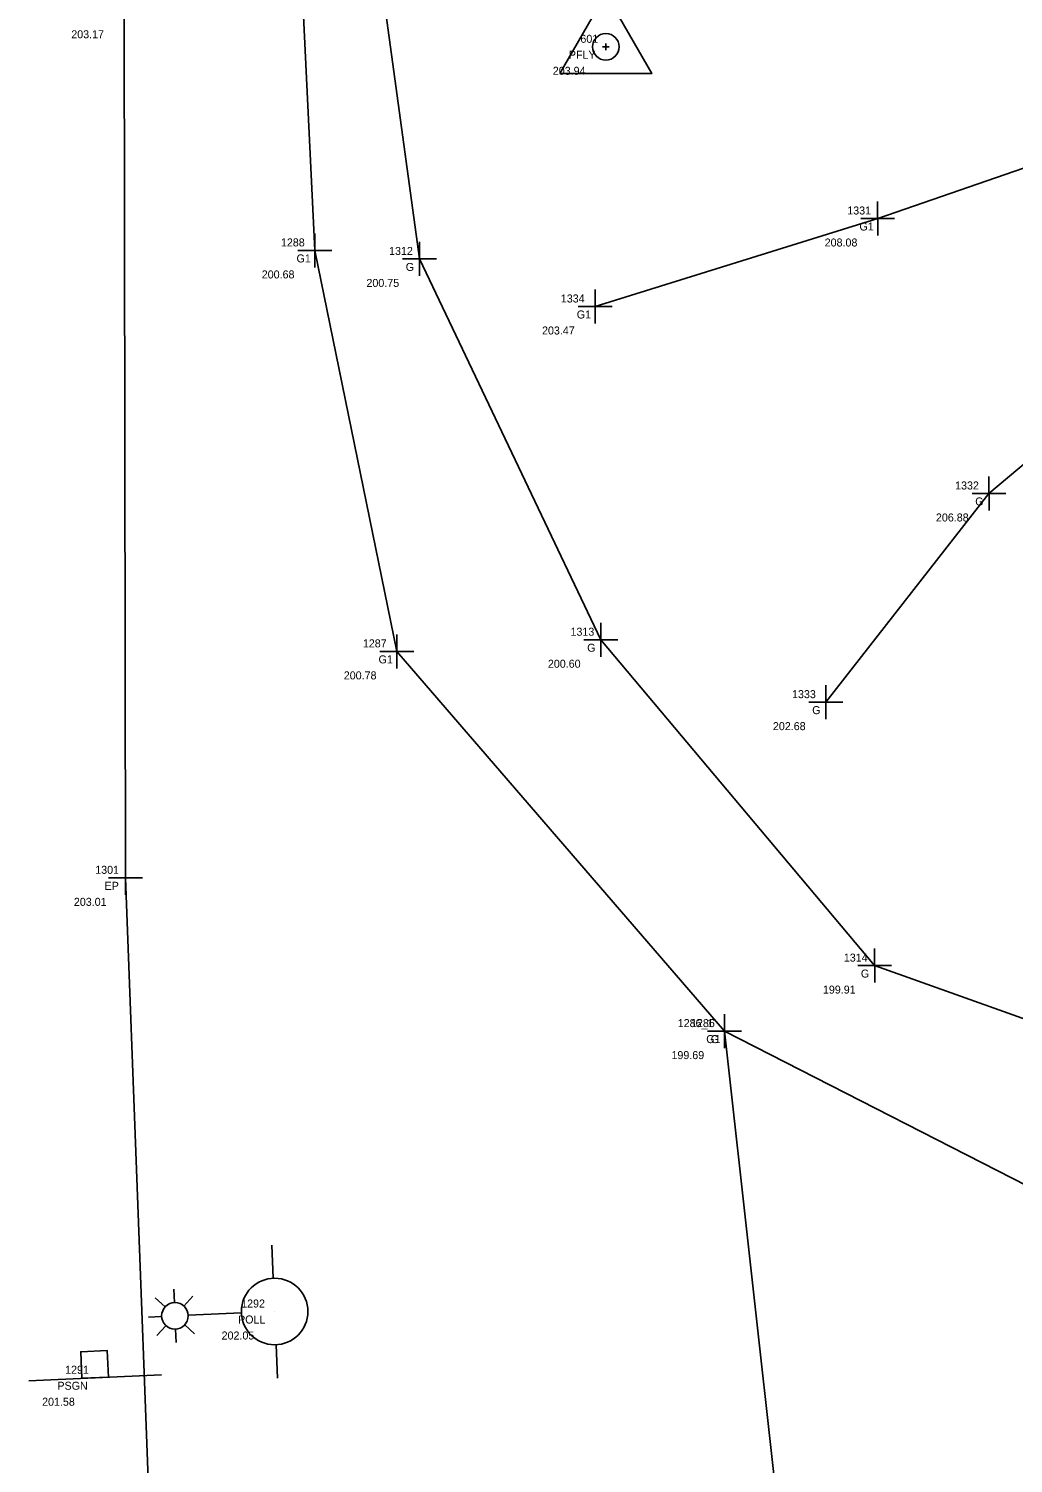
# Model space of a CAD drawing. Extents: x 1158983 to 1160032, y 610902 to 611573.
# Drawn here: x 1159623.8 to 1159660.7, y 611136.1 to 611189.9 of the extents above; entities that cross this region are included whole.
import ezdxf

# ---------------------------------------------------------------- set-up
doc = ezdxf.new("R2010")
doc.units = 0
for name, color, linetype in [('Default', 7, 'Continuous'), ('S_Control_Temp_Traverse', 7, 'Continuous'), ('S_Field_Code', 7, 'Continuous'), ('S_Ground_Elevation', 7, 'Continuous'), ('S_Point_Elevation', 7, 'Continuous'), ('S_Point_Name', 7, 'Continuous'), ('S_Roadway_Edge_Pavement', 7, 'Continuous'), ('S_Survey_Shot', 7, 'Continuous'), ('S_Traffic_Sign_SinglePost', 7, 'Continuous'), ('S_Utilities_Pole_StreetLight', 7, 'Continuous')]:
    doc.layers.add(name, color=color, linetype=linetype)

msp = doc.modelspace()

# ---------------------------------------------------------------- linework, layer by layer
at = {"layer": 'Default'}
for p, q in [((1159632.986, 611141.798), (1159632.986, 611141.798)), ((1159626.254, 611139.315), (1159626.254, 611139.315))]:
    msp.add_line(p, q, dxfattribs=at)
at = {"layer": 'S_Control_Temp_Traverse'}
for p, q in [((1159645.407, 611189.336), (1159645.407, 611189.086)), ((1159645.283, 611189.211), (1159645.532, 611189.211))]:
    msp.add_line(p, q, dxfattribs=at)
msp.add_lwpolyline([(1159643.679, 611188.213), (1159647.136, 611188.213), (1159645.407, 611191.207)], close=True, dxfattribs=at)
msp.add_circle((1159645.407, 611189.211), 0.499, dxfattribs=at)
at = {"layer": 'S_Ground_Elevation'}
for points in [[(1159638.219, 611212.373), (1159636.237, 611197.229), (1159638.417, 611181.257), (1159645.222, 611166.982), (1159655.488, 611154.766), (1159667.117, 611150.624)], [(1159639.791, 610965.535), (1159645.775, 610991.151), (1159650.157, 611007.062), (1159651.628, 611033.422), (1159658.582, 611070.749), (1159658.53, 611093.77), (1159652.818, 611125.693), (1159649.858, 611152.31), (1159637.568, 611166.545), (1159634.492, 611181.577), (1159633.715, 611197.621), (1159631.631, 611207.348)], [(1159676.206, 611189.524), (1159669.173, 611186.301), (1159664.473, 611185.83), (1159655.602, 611182.774), (1159645.003, 611179.475)], [(1159679.856, 611189.617), (1159675.97, 611186.023), (1159672.274, 611182.947), (1159659.776, 611172.465), (1159653.662, 611164.642)], [(1159656.699, 610987.169), (1159659.81, 610998.002), (1159662.56, 611006.154), (1159673.42, 611011.162), (1159680.629, 611024.514), (1159686.412, 611068.065), (1159676.665, 611103.478), (1159674.701, 611128.373), (1159674.028, 611141.093), (1159662.925, 611145.632), (1159649.858, 611152.31)]]:
    msp.add_lwpolyline(points, dxfattribs=at)
at = {"layer": 'S_Roadway_Edge_Pavement'}
msp.add_lwpolyline([(1159649.054, 610914.248), (1159642.457, 610938.482), (1159637.798, 610964.216), (1159632.683, 610994.591), (1159630.828, 611030.062), (1159633.705, 611071.605), (1159635.455, 611089.542), (1159635.84, 611098.138), (1159632.325, 611112.966), (1159628.263, 611134.867), (1159627.396, 611158.056), (1159627.348, 611190.58), (1159627.149, 611191.432), (1159625.27, 611191.93), (1159624.992, 611193.489), (1159626.722, 611215.216)], dxfattribs=at)
at = {"layer": 'S_Survey_Shot'}
for p, q in [((1159655.604, 611182.138), (1159655.601, 611183.411)), ((1159654.966, 611182.773), (1159656.239, 611182.776)), ((1159655.602, 611182.774), (1159655.602, 611182.774)), ((1159634.494, 611180.94), (1159634.491, 611182.213)), ((1159638.419, 611180.621), (1159638.416, 611181.893)), ((1159633.856, 611181.575), (1159635.129, 611181.578)), ((1159634.492, 611181.577), (1159634.492, 611181.577)), ((1159637.781, 611181.256), (1159639.054, 611181.258)), ((1159638.417, 611181.257), (1159638.417, 611181.257)), ((1159645.005, 611178.838), (1159645.002, 611180.111)), ((1159644.367, 611179.473), (1159645.64, 611179.476)), ((1159645.003, 611179.475), (1159645.003, 611179.475)), ((1159659.778, 611171.829), (1159659.775, 611173.102)), ((1159659.14, 611172.464), (1159660.413, 611172.467)), ((1159659.776, 611172.465), (1159659.776, 611172.465)), ((1159645.224, 611166.345), (1159645.221, 611167.618)), ((1159637.569, 611165.908), (1159637.566, 611167.181)), ((1159644.586, 611166.98), (1159645.859, 611166.983)), ((1159645.222, 611166.982), (1159645.222, 611166.982)), ((1159636.932, 611166.543), (1159638.204, 611166.546)), ((1159637.568, 611166.545), (1159637.568, 611166.545)), ((1159653.664, 611164.006), (1159653.661, 611165.278)), ((1159653.026, 611164.641), (1159654.299, 611164.643)), ((1159653.662, 611164.642), (1159653.662, 611164.642)), ((1159627.397, 611157.42), (1159627.394, 611158.692)), ((1159626.759, 611158.054), (1159628.032, 611158.057)), ((1159627.396, 611158.056), (1159627.396, 611158.056)), ((1159655.49, 611154.13), (1159655.487, 611155.402)), ((1159654.852, 611154.764), (1159656.125, 611154.767)), ((1159655.488, 611154.766), (1159655.488, 611154.766)), ((1159649.86, 611151.674), (1159649.857, 611152.947)), ((1159649.86, 611151.674), (1159649.857, 611152.947)), ((1159649.222, 611152.309), (1159650.495, 611152.312)), ((1159649.222, 611152.309), (1159650.495, 611152.312)), ((1159649.858, 611152.31), (1159649.858, 611152.31)), ((1159649.858, 611152.31), (1159649.858, 611152.31))]:
    msp.add_line(p, q, dxfattribs=at)
at = {"layer": 'S_Traffic_Sign_SinglePost'}
msp.add_line((1159628.747, 611139.424), (1159623.762, 611139.205), dxfattribs=at)
msp.add_lwpolyline([(1159626.753, 611139.336), (1159625.756, 611139.293), (1159625.712, 611140.29), (1159626.709, 611140.334)], close=True, dxfattribs=at)
at = {"layer": 'S_Utilities_Pole_StreetLight'}
for p, q in [((1159632.932, 611143.044), (1159632.877, 611144.291)), ((1159629.225, 611142.133), (1159629.204, 611142.632)), ((1159628.879, 611141.972), (1159628.511, 611142.309)), ((1159629.584, 611142.002), (1159629.922, 611142.37)), ((1159628.749, 611141.613), (1159628.25, 611141.591)), ((1159631.74, 611141.743), (1159629.746, 611141.656)), ((1159628.91, 611141.267), (1159628.573, 611140.899)), ((1159629.269, 611141.136), (1159629.291, 611140.637)), ((1159629.615, 611141.297), (1159629.983, 611140.96)), ((1159633.041, 611140.551), (1159633.095, 611139.305))]:
    msp.add_line(p, q, dxfattribs=at)
for centre, radius in [((1159632.986, 611141.798), 1.248), ((1159629.247, 611141.635), 0.499)]:
    msp.add_circle(centre, radius, dxfattribs=at)

# ---------------------------------------------------------------- texts
at = {"layer": 'S_Field_Code'}
for s, p in [('PFLY', (1159644.021, 611188.761)), ('G1', (1159654.918, 611182.324)), ('G1', (1159633.807, 611181.127)), ('G', (1159637.903, 611180.807)), ('G1', (1159644.318, 611179.025)), ('G', (1159659.261, 611172.015)), ('G', (1159644.708, 611166.532)), ('G1', (1159636.883, 611166.095)), ('G', (1159653.147, 611164.192)), ('EP', (1159626.609, 611157.606)), ('G', (1159654.973, 611154.316)), ('G1', (1159649.173, 611151.86)), ('G', (1159649.343, 611151.86)), ('POLL', (1159631.614, 611141.348)), ('PSGN', (1159624.839, 611138.865))]:
    msp.add_text(s, height=0.3, dxfattribs=at).set_placement(p)
at = {"layer": 'S_Point_Elevation'}
for s, p in [('203.17', (1159625.359, 611189.53)), ('203.94', (1159643.418, 611188.161)), ('208.08', (1159653.614, 611181.724)), ('200.68', (1159632.503, 611180.527)), ('200.75', (1159636.429, 611180.207)), ('203.47', (1159643.014, 611178.425)), ('206.88', (1159657.787, 611171.415)), ('200.60', (1159643.234, 611165.932)), ('200.78', (1159635.579, 611165.495)), ('202.68', (1159651.673, 611163.592)), ('203.01', (1159625.456, 611157.006)), ('199.91', (1159653.549, 611153.716)), ('199.69', (1159647.869, 611151.26)), ('199.69', (1159647.869, 611151.26)), ('202.05', (1159630.997, 611140.748)), ('201.58', (1159624.265, 611138.265))]:
    msp.add_text(s, height=0.3, dxfattribs=at).set_placement(p)
at = {"layer": 'S_Point_Name'}
for s, p in [('601', (1159644.453, 611189.361)), ('1331', (1159654.462, 611182.924)), ('1288', (1159633.222, 611181.727)), ('1312', (1159637.277, 611181.407)), ('1334', (1159643.718, 611179.625)), ('1332', (1159658.506, 611172.615)), ('1313', (1159644.082, 611167.132)), ('1287', (1159636.295, 611166.695)), ('1333', (1159652.391, 611164.792)), ('1301', (1159626.257, 611158.206)), ('1314', (1159654.333, 611154.916)), ('1286_1', (1159648.103, 611152.46)), ('1286', (1159648.602, 611152.46)), ('1292', (1159631.73, 611141.948)), ('1291', (1159625.128, 611139.465))]:
    msp.add_text(s, height=0.3, dxfattribs=at).set_placement(p)

doc.saveas('drawing.dxf')
